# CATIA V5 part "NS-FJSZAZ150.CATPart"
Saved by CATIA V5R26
Part number: NS-FJSZAZ150
Bounding box of the stored display mesh (mm): x -60 to 120, y 0 to 198, z -110.177 to 60
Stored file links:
  R:\Document\坂尻\その他\ナベヤデータ変換\安全カバーキャスター\MCBJSZAZ150\NS-FJSZAZ150.CATPart
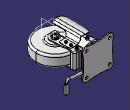
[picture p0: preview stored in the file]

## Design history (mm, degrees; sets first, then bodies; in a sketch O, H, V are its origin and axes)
Body1 (main body)
  Solid1: solid without history
  Body2
    Solid2: solid without history
  Assemble1: tool Body2
  Body3
    Solid3: solid without history
  Assemble2: tool Body3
